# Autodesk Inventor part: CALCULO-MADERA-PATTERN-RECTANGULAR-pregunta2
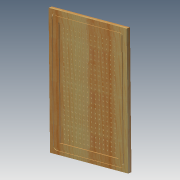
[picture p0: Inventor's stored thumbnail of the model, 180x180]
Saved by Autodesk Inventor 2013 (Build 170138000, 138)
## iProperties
Created: 2012-03
Part Number: CALCULO-MADERA-PATTERN-RECTANGULAR-pregunta2
Material: Generic
Document SubType Name: Modeling
Designer: julian.chica
Mass: 462.834 g
Surface Area: 1534.07 cm^2
Volume: 462.834 cm^3
Density: 1 g/cm^3
Author: julian.chica
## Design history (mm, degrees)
node "XZ- Plane Front"
sketch "Sketch7"
  geometry: L1 (-100, 150)-(100, 150); L2 (100, 150)-(100, -150); L3 (100, -150)-(-100, -150); L4 (-100, -150)-(-100, 150); 3 further points
  constraints: 8 end point, 2 midpoint, 2 parallel, 1 horizontal, 1 horizontal alignment, 1 perpendicular, 1 vertical alignment
  dimensions: "d4" = 300 distance of L1.end L2.end; "d5" = 200 distance of L1.start L1.end
extrude "Extrusion1" new body sketch "Sketch7" stored distance "d6" = 10; taper "d7" = 0 deg
sketch "Sketch8"
  geometry: L1 (100, 150)-(100, -150) reference; L2 (-100, 150)-(100, 150) reference; L3 (-100, -150)-(-100, 150) reference; L4 (100, -150)-(-100, -150) reference; L5 (75, 125)-(75, -125); L6 (75, -125)-(-75, -125); L7 (-75, -125)-(-75, 125); L8 (-75, 125)-(75, 125); 1 further point
  constraints: 8 end point, 3 other
  dimensions: "d8" = 25 distance between parallel lines of L3 L7
extrude "Extrusion2" cut sketch "Sketch8" distance "d9" = 3; taper "d10" = 0 deg
sketch "Sketch9"
  geometry: L1 (-75, 125)-(75, 125) reference; L2 (75, 125)-(75, -125) reference; L3 (75, -125)-(-75, -125) reference; L4 (-75, -125)-(-75, 125) reference; L5 (-82, 142)-(82, 142); L6 (92, 132)-(92, -132); L7 (82, -142)-(-82, -142); L8 (-92, -132)-(-92, 132); L9 (-87, 132)-(-87, -132); L10 (-82, -137)-(82, -137); L11 (87, -132)-(87, 132); L12 (82, 137)-(-82, 137); A1 r 10 centre (-82, 132) between (-82, 142) and (-92, 132); A2 r 10 centre (82, 132) between (92, 132) and (82, 142); A3 r 10 centre (-82, -132) between (-92, -132) and (-82, -142); A4 r 10 centre (82, -132) between (82, -142) and (92, -132); A5 r 5 centre (-82, -132) between (-87, -132) and (-82, -137); A6 r 5 centre (82, -132) between (82, -137) and (87, -132); A7 r 5 centre (82, 132) between (87, 132) and (82, 137); A8 r 5 centre (-82, 132) between (-82, 137) and (-87, 132); 1 further point
  constraints: 16 end point, 16 point on circle, 8 centre point, 8 tangent, 3 equal radius, 10 other
  dimensions: "d11" = 17 distance between parallel lines of L5 L1; "d12" = 10 radius of A1; "d13" = 5 distance between parallel lines of L8 L9
extrude "Extrusion3" cut sketch "Sketch9" distance "d14" = 2; taper "d15" = 0 deg
sketch "Sketch10"
  geometry: L1 (-75, 125)-(-75, -125) reference; L2 (-75, -125)-(75, -125) reference; C1 r 1.5 at (-65, -115); 1 further point
  constraints: 1 centre point
  dimensions: "DISTANCIA_B" = 10 distance from line of C1.centre L2; "DISTANCIA_A" = 10 distance from line of L1 C1.centre; "d18" = 3 diameter of C1
extrude "Extrusion4" cut sketch "Sketch10" distance "d19" = 10; taper "d20" = 0 deg
sketch "Sketch11"
  geometry: L1 (-82, -137)-(82, -137) reference; L2 (87, -132)-(87, 132) reference; L3 (82, 137)-(-82, 137) reference; L4 (-87, 132)-(-87, -132) reference; L5 (-75, 125)-(75, 125) reference; L6 (75, 125)-(75, -125) reference; L7 (75, -125)-(-75, -125) reference; L8 (-75, -125)-(-75, 125) reference; A1 r 5 centre (-82, -132) between (-87, -132) and (-82, -137) reference; A2 r 5 centre (82, -132) between (82, -137) and (87, -132) reference; A3 r 5 centre (82, 132) between (87, 132) and (82, 137) reference; A4 r 5 centre (-82, 132) between (-82, 137) and (-87, 132) reference; 1 further point
  dimensions: "d27" = 12 distance between parallel lines of L2 L6 (derived)
body "Solid1"
pattern_linear "Rectangular Pattern1" dims "DISTANCIA_C" = 10
other parameters: "d0" = 0
